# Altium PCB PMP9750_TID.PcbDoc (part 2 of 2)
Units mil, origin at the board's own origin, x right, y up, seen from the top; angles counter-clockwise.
Board outline 3800 x 2050 mil, 2 copper layers (Top Layer, Bottom Layer), stack 62 mil thick; 72 components, 37 nets, 177 pads, 17 vias.
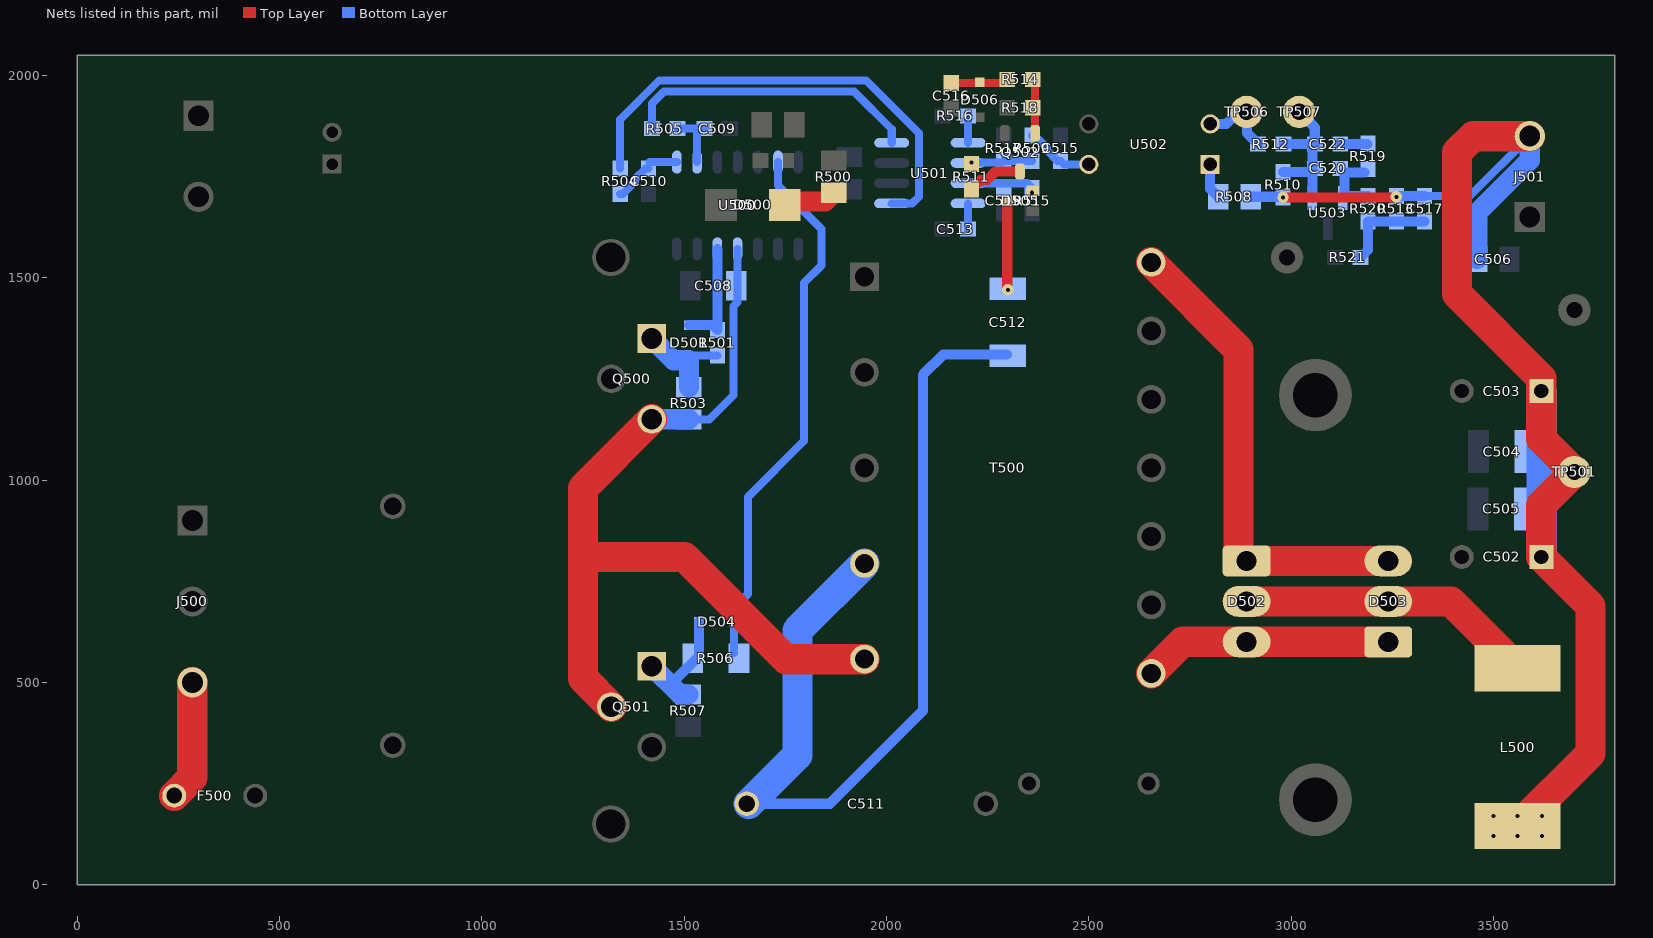
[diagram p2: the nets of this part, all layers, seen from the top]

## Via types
v1: diameter 28, hole 10, Top Layer to Bottom Layer, 17 vias

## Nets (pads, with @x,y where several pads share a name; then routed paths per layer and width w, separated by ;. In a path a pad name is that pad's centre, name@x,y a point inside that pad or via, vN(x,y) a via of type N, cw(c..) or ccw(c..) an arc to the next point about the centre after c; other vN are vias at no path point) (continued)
NetC508_2: C508.2 Q500.3 Q501.2 R503.2 T500.5 U500.11 | length 2162.4
  Top Layer w75: 1290,810 1500,810 1752.44,557.56 T500.5@1945.67,557.56 ; Q501.2@1320,440 1250,510 1250,980 Q500.3@1420,1150
  Bottom Layer w20: R503.2@1512,1149.6 1562,1149.6 1622,1209.6 1622,1429.6 1632,1439.6 U500.11@1632,1571.22
  Bottom Layer w50: Q500.3@1420,1150 1511.6,1150 R503.2@1512,1149.6
NetC509_1: C509.1 R505.2 U500.2 | length 139.7
  Bottom Layer w20: R505.2@1483.5,1868.5 C509.1@1550.5,1868.5 ; U500.2@1532,1785.78 C509.1@1532,1858.52
NetC510_1: C510.1 R504.2 U500.1 | length 167.1
  Bottom Layer w20: R504.2@1342,1707 1348.34,1707 1378.57,1737.24 1378.57,1743.58 1404.99,1770 C510.1@1412,1770 ; C510.1@1414.72,1785.78 U500.1@1482,1785.78
NetC512_2: C512.2 D505.3 | length 218.5
  Top Layer w25: v1@2298.5,1471.5 D505.3@2298.5,1690
  other v1: 2300,1470
NetC513_1: C513.1 U501.4 | length 63.1
  Bottom Layer w20: C513.1@2201.92,1620.43 U501.4@2201.92,1683.5
NetC515_1: C515.1 R509.2 U502.4 | length 161.3
  Bottom Layer w20: R509.2@2360,1851.5 2366.34,1851.5 2396.57,1821.26 2396.57,1814.92 2422.99,1788.5 C515.1@2430,1788.5 ; C515.1@2438.5,1780 U502.4@2500,1780
NetC516_2: C516.2 D506.1 R514.1 | length 142
  Top Layer w20: C516.2@2160,1981.5 2290,1981.5 R514.1@2298.5,1990
NetC517_2: C517.2 R513.1 R520.2 R521.2 | length 236.2
  Bottom Layer w25: R521.2@3171.5,1550 3190,1568.5 R520.2@3190,1638.5 C517.2@3330,1638.5
NetC519_1: C519.1 D505.2 R515.2 U501.3 | length 163.1
  Bottom Layer w20: U501.3@2201.92,1733.5 2348,1733.5 R515.2@2360,1721.5
  other v1: 2360,1710
NetC520_1: C520.1 R519.2 R520.1 U503.2 | length 167
  Bottom Layer w25: R519.2@3181.5,1760 3131.5,1760 3131.5,1701.5 R520.1@3190,1701.5
NetC520_2: C520.2 C522.2 R510.1 R512.2 TP507.1 U503.1 | length 360.3
  Bottom Layer w25: R510.1@2980,1761.5 C520.2@3044.09,1761.5 ; R512.2@2981.5,1830 3046.69,1830 3052.6,1824.09 U503.1@3052.6,1697.4 ; TP507.1@3020,1910 3058.5,1871.5 C522.2@3058.5,1830
NetC522_1: C522.1 R519.1 | length 67
  Bottom Layer w25: C522.1@3121.5,1830 R519.1@3188.5,1830
NetD500_2: D500.2 R500.2 | length 138.2
  Top Layer w50: D500.2@1740.74,1688.5 1848.5,1688.5 R500.2@1870,1710
NetD501_1: D501.1 R501.1 U500.12 | length 275
  Bottom Layer w25: D501.1@1512,1382.91 1570.19,1382.91 R501.1@1582,1371.1 U500.12@1582,1571.22
NetD501_2: D501.2 Q500.1 R501.2 R503.1 | length 255.8
  Bottom Layer w20: D501.2@1512,1296.3 1523.81,1308.11 R501.2@1582,1308.11
  Bottom Layer w50: Q500.1@1420,1350 1473.7,1296.3 D501.2@1512,1296.3 R503.1@1512,1229.6
NetD502_1: D502.1 D503.3 T500.12 | length 1185.5
  Top Layer w75: T500.12@2654.33,1537.87 2870,1322.2 2870,820 D502.1@2890,800 D503.3@3240,800
NetD502_3: D502.3 D503.1 T500.6 | length 617.9
  Top Layer w75: T500.6@2654.33,522.13 2732.2,600 D502.3@2890,600 D503.1@3240,600
NetD504_1: D504.1 R506.1 U500.6 | length 1347.5
  Bottom Layer w20: R506.1@1623.31,572.44 D504.1@1623.31,650 1623.31,683.89 1657.87,718.45 1657.87,958.45 1795.75,1096.33 1795.75,1486.83 1839.56,1530.64 1839.56,1620.36 1732,1727.92 U500.6@1732,1785.78
NetD504_2: D504.2 Q501.1 R506.2 R507.1 | length 278.4
  Bottom Layer w25: 1484.17,512.36 1536.69,564.88 D504.2@1536.69,650
  Bottom Layer w50: Q501.1@1420,540 1490,470 R507.1@1510,470
NetF500_2: F500.2 J500.3 | length 298.6
  Top Layer w75: F500.2@240,220 284.83,264.83 J500.3@284.83,500
NetQ502_1: Q502.1 R514.2 R518.1 | length 126.9
  Top Layer w20: Q502.1@2367.4,1857.24 R514.2@2367.4,1984.09
NetQ502_3: Q502.3 R511.1 | length 138.3
  Top Layer w25: R511.1@2210,1718.5 2232.93,1741.44 2249.07,1741.44 2270.39,1762.76 Q502.3@2330,1762.76
NetR504_1: R504.1 U501.5 | length 1184.4
  Bottom Layer w20: R504.1@1342,1770 1342,1891.42 1438.45,1987.87 1949.05,1987.87 2080,1856.93 2080,1700 2063.5,1683.5 U501.5@2012.94,1683.5
NetR505_1: R505.1 U501.8 | length 738.7
  Bottom Layer w20: R505.1@1420.5,1868.5 1420.5,1930.5 1450,1960 1920,1960 2012.94,1867.06 U501.8@2012.94,1833.5
NetR508_1: R508.1 U502.1 | length 88.3
  Bottom Layer w25: U502.1@2800,1780 2800,1720 R508.1@2820,1700
NetR509_1: R509.1 R511.2 R517.2 U501.2 | length 145.9
  Bottom Layer w20: v1(2210,1784.45) R517.2@2285.94,1784.45 ; R517.2@2290,1788.5 R509.1@2360,1788.5
NetR512_1: R512.1 TP506.1 U502.2 | length 194.2
  Bottom Layer w25: U502.2@2800,1880 2840,1880 2870,1910 TP506.1@2890,1910 2891.3,1908.7 2891.3,1857.2 R512.1@2918.5,1830
NetR516_2: R516.2 U501.1 | length 66.1
  Bottom Layer w20: U501.1@2201.92,1833.5 R516.2@2201.92,1899.57
VCS: C511.1 C512.1 T500.4 | length 2295.4
  Bottom Layer w25: C511.1@1660,200 1860,200 2090,430 2090,1260 2140,1310 C512.1@2297.32,1310
  Bottom Layer w75: C511.1@1660,200 1780,320 1780,628.11 T500.4@1945.67,793.78
VOUT: C502.1 C503.1 C504.1 C505.1 C506.1 C517.1 J501.2 L500.2 R508.2 R510.2 R513.2 TP501.1 | length 3718.2
  Top Layer w25: v1(2980,1698.5) v1@3258.5,1698.5
  Top Layer w75: L500.2@3560,145.12 3740,325.12 3740,688.43 C502.1@3618.43,810 3618.43,938.43 TP501.1@3700,1020 3618.43,1101.57 C503.1@3618.43,1220 3618.43,1251.57 3410,1460 3410,1810 3450,1850 J501.2@3590,1850
  Bottom Layer w20: C517.1@3330,1701.5 3441.5,1701.5 J501.2@3590,1850
  Bottom Layer w25: R508.2@2900,1700 R510.2@2978.5,1700 ; R513.2@3260,1701.5 C517.1@3330,1701.5
  Bottom Layer w50: C506.1@3460,1546 3460,1660 3590,1790 J501.2@3590,1850
  Bottom Layer w75: C503.1@3618.43,1220 C502.1@3620,820 ; 3628.43,1020 TP501.1@3700,1020
  other v1: 3500,120 3560,120 3620,120 3500,170 3560,170 3620,170 3260,1700
VSEC: D502.2 D503.2 L500.1 | length 738.4
  Top Layer w75: D502.2@2890,700 D503.2@3240,700 3394.88,700 L500.1@3560,534.88
pads on no net: J500.2 T500.1 T500.2 T500.3 T500.7 T500.9 T500.11 U500.4 U500.8 U500.9 U500.10 U500.14

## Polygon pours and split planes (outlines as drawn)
GND2 on Top Layer "GND2" (solid, remove dead copper, pour order 21): 2780,2020 2800,2040 2830,2040 3770,2040 3790,2020 3790,2000 3790,1860 3790,30 3770,10 3750,10 2640,10 2620,30 2620,100 2620,380 2530,470 2530,480 2530,540 2530,985.04 2530,1260 2600,1330 2610,1340 2610,1570 2640,1600 2780,1740 2780,1768 2780,1910 2780,1950 2780,2020
GND on Top Layer "GND" (solid, remove dead copper, pour order 18): 30,2040 10,2020 10,2000 10,30 30,10 50,10 2360,10 2380,30 2380,60 2380,190 2380,260 2360,280 2230,410 2230,620 2230,870 2230,1250 2230,1510 2420,1700 2520,1800 2520,1830 2520,2020 2500,2040
NetF500_2 on Top Layer "F500_2" (solid, remove dead copper, pour order 16): 170,180 150,200 150,230 150,520 170,540 270,540 320,540 340,520 340,500 340,290 340,200 320,180
VSEC on Top Layer "VSEC" (solid, remove dead copper, pour order 12): 2850,730 2840,720 2840,680 2850,670 2860,670 2920,670 3010,670 3310,670 3350,630 3350,580 3350,500 3350,460 3370,440 3490,440 3650,440 3670,460 3670,480 3670,600 3540,730 3460,730 3380.58,730 3380,729.42 3379.42,730 3260,730
NetD502_1 on Top Layer "D502_1" (solid, remove dead copper, pour order 10): 2610,1570 2620,1580 2680,1580 2730,1580 2740,1580 2920,1400 2930,1390 2930,1370 2930,1300 2930,1160 2930,1150 3000,1080 3100,980 3130,980 3280,980 3300,960 3300,800 3280,780 3270,770 3230,770 2910,770 2850,770 2830,770 2820,780 2820,850 2820,910 2740,990 2740,1060 2740,1370 2610,1500
NetD502_3 on Top Layer "D502_3" (solid, remove dead copper, pour order 8): 2630,540 2630,610 2640,620 2710,620 2784.25,620 3280,620 3290,610 3290,600 3290,570 3290,540 3290,490 3280,480 3270,480 2650,480 2630,500
B+ on Top Layer "B+" (solid, remove dead copper, pour order 4): 400,200 420,180 440,180 520,180 660,180 880,400 1130,650 1130,1020 1324.92,1215.07 1324.92,1260 1324.92,1265.08 1300,1290 1290,1290 1180,1290 950,1060 950,790 400,240
NetC508_2 on Top Layer "C508_2" (solid, remove dead copper, pour order 2): 1410,1190 1390,1170 1360,1140 1230,1010 1230,710 1230,480 1290,420 1307.99,420 1307.99,597.99 1360,650 1380,650 1590,650 1720,520 1860,520 1960,520 1970,520 1990,540 1990,570 1930,630 1840,630 1830,630 1460,1000 1460,1170 1440,1190
GND2 on Bottom Layer "GND2" (solid, remove dead copper, pour order 21): 2780,2020 2800,2040 2830,2040 3770,2040 3790,2020 3790,2000 3790,1860 3790,30 3770,10 3750,10 2640,10 2620,30 2620,100 2620,380 2530,470 2530,480 2530,540 2530,985.04 2530,1260 2600,1330 2610,1340 2610,1570 2640,1600 2780,1740 2780,1768 2780,1910 2780,1950 2780,2020
GND on Bottom Layer "GND" (solid, remove dead copper, pour order 18): 30,2040 10,2020 10,2000 10,30 30,10 50,10 2360,10 2380,30 2380,60 2380,190 2380,260 2360,280 2230,410 2230,620 2230,870 2230,1250 2230,1510 2420,1700 2520,1800 2520,1830 2520,2020 2500,2040
VOUT on Bottom Layer "Vout" (solid, remove dead copper, pour order 14): 3480,20 3460,40 3460,80 3460,220 3480,240 3530,290 3532.87,292.87 3532.87,613.59 3532.87,1172.87 3590,1230 3590.73,1229.27 3636.77,1229.27 3720.73,1229.27 3740,1210 3740,1180 3740,40 3720,20
VCS on Bottom Layer "VCS" (solid, remove dead copper, pour order 6): 1970,840 1990,820 1990,800 1990,780 1990,720 1870,600 1870,580 1870,470 1870,350 1870,250 1840,220 1800,220 1740,220 1730,210 1730,180 1730,170 1720,160 1690,160 1630,160 1620,170 1620,200 1620,210 1620,240 1740,360 1740,380 1740,820 1760,840

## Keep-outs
Keep-Out Layer:
  text ".Layer_Name" at 577,-858.49 h60

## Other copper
Top Layer:
  text ".Layer_Name" at 577,-858.49 h60
Bottom Layer:
  text ".Layer_Name" at 577,-858.49 h60

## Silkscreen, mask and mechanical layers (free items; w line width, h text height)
Top Overlay:
  lines w10: 2060,1840 2200,1840 2230,1870 ; 2410,1910 2430,1910 2440,1920 2480,1920
  text ".PRJ_Number" at 100,1330 h60
  text ".PCB_Rev" at 700,1330 h60
  text "-" at 30,870 h60
  text "NC" at 20,680 h35
  text "+" at 30,470 h60
  text ".Layer_Name" at 577,-858.49 h60
Bottom Overlay:
  lines w10: 1370,1480 1370,1430 1400,1400 1460,1400 ; 2290,1610 2290,1590 2320,1560 2370,1560 2390,1540 2390,1500 ; 2930,1540 2930,1590 2980,1640 2980,1650 ; 3100,1880 3100,1920 3130,1950 3190,1950 ; 3220,1590 3230,1580 3230,1440 ; 3190,1950 3190,2030 3540,2030 3540,1980 3540,1820 3360,1820 3340,1840 3340,1910 3320,1930 3220,1930 3210,1930 3190,1950
  text "-" at 110,870 h60
  text "NC" at 110,670 h35
  text "+" at 110,470 h60
  text ".Layer_Name" at 577,-858.49 h60
Top Paste:
  text ".Layer_Name" at 577,-858.49 h60
Bottom Paste:
  text ".Layer_Name" at 577,-858.49 h60
Top Solder:
  text ".Layer_Name" at 577,-858.49 h60
  text ".Layer_Name" at 577,-858.49 h60
Bottom Solder:
  text ".Layer_Name" at 577,-858.49 h60
Drill Guide:
  text ".Layer_Name" at 577,-858.49 h60
M1 Board Outline:
  the board outline again, w10
  text ".Layer_Name" at 577,-858.49 h60
M2 Board Dimensions:
  rectangle: 125,-400 500,-275
  rectangle: 0,-275 125,-150
  lines w7: 0,-275 1000,-275 ; 125,-400 125,-150 ; 250,-400 250,-150 ; 500,-400 500,-150 ; 750,-400 750,-150 ; 0,-400 0,-150 1000,-150 1000,-400 0,-400
  text ".Layer_Name" at 577,-858.49 h60
M3 3D STEP Top:
  text ".Layer_Name" at 577,-858.49 h60
M4 3D STEP Bottom:
  text ".Layer_Name" at 577,-858.49 h60
M5 Assembly Top:
  lines w10: -292,-930.17 6308,-930.17 ; -292,-726.83 6310,-726.83 ; -292,-523.5 -292,-1133.5 3713,-1133.5 6310,-1133.5 6310,-523.5 -291.5,-523.5 -291.5,-1133.5 1284,-1133.5 ; 2173,-1133.5 2173,-523.5 ; 3440,-726.83 3440,-523.5 ; 4280,-726.83 4280,-523.5 ; 4902,-1140 4902,-937.17
  text "COMPONENTS MARKED 'DNP' SHOULD NOT BE POPULATED." at 1153.5,-318.5 h60
  text "ASSEMBLY VARIANT:" at 1153,-434 h60
  text ".VariantName" at 2189,-434 h60
  text "PCB VIEWED FROM TOP SIDE" at -228.5,-655.67 h60
  text "BOARD #:" at 2248,-655.67 h60
  text ".PRJ_Number" at 2793.5,-655.67 h60
  text "REV:" at 3638,-655.67 h60
  text ".PCB_Rev" at 3929.5,-655.67 h60
  text "SVN REV:" at 4476,-655.67 h60
  text ".VersionControl_RevNumber" at 4982,-655.67 h60
  text "TID #:" at 2248,-859 h60
  text ".TID" at 2793.5,-859 h60
  text "PLOT NAME =" at -228.5,-1064.34 h60
  text ".plot_File_Name" at 577,-1064.34 h60
  text "GENERATED    :" at 2250,-1064.34 h60
  text ".Print_Date" at 3119.5,-1064.34 h60
  text ".Print_Time" at 3848.5,-1064.34 h60
  text "TEXAS INSTRUMENTS" at 5113,-1064.34 h60
M6 Assembly Bottom:
  lines w10: -292.5,-727.33 6309.5,-727.33 ; -290.5,-930.67 6309.5,-930.67 ; 1115.5,-1140.5 1115.5,-937.67 ; 1737.5,-727.33 1737.5,-524 ; 2577.5,-727.33 2577.5,-524 ; 3844.5,-1134 3844.5,-524 ; 4733.5,-1134 6309,-1134 6309,-524 -292.5,-524 -292.5,-1134 2304.5,-1134 6309.5,-1134 6309.5,-524
  text "COMPONENTS MARKED 'DNP' SHOULD NOT BE POPULATED." at 6102,-318 h60
  text ".VariantName" at 5058,-434 h60
  text "ASSEMBLY VARIANT:" at 6097,-434 h60
  text ".VersionControl_RevNumber" at 1035.5,-656.17 h60
  text "SVN REV:" at 1541.5,-656.17 h60
  text ".PCB_Rev" at 2088,-656.17 h60
  text "REV:" at 2379.5,-656.17 h60
  text ".PRJ_Number" at 3224,-656.17 h60
  text "BOARD #:" at 3769.5,-656.17 h60
  text "PCB VIEWED FROM BOTTOM SIDE" at 6246,-656.17 h60
  text ".TID" at 3224,-859.5 h60
  text "TID #:" at 3769.5,-859.5 h60
  text "TEXAS INSTRUMENTS" at 904.5,-1064.84 h60
  text ".Print_Time" at 2169,-1064.84 h60
  text ".Print_Date" at 2898,-1064.84 h60
  text "GENERATED    :" at 3767.5,-1064.84 h60
  text ".plot_File_Name" at 5440.5,-1064.84 h60
  text "PLOT NAME =" at 6246,-1064.84 h60
M9 Title Sheet:
  drawing of 57 lines, arcs and shapes, not listed
  text "1" at 739.84,8036.5 h70
  text "2" at 3235.5,8036.5 h70
  text "3" at 5724.84,8036.5 h70
  text "4" at 8231.51,8036.5 h70
  text "5" at 10730.5,8036.5 h70
  text "6" at 13235.5,8036.5 h70
  text "A" at -416.5,6893.5 h70
  text "A" at 14383.5,6893.5 h70
  text "B" at -416.5,4513.5 h70
  text "B" at 14383.5,4513.5 h70
  text "C" at -416.5,2138.5 h70
  text "C" at 14383.5,2138.5 h70
  text "PROJECT TITLE:" at 11343.5,277.5 h45
  text ".PRJ_Title" at 11393.5,144.17 h70
  text "DESIGNED FOR:" at 11343.5,-23.5 h45
  text ".PRJ_Customer" at 11393.5,-163.5 h70
  text "D" at -416.5,-231.5 h70
  text "D" at 14383.5,-231.5 h70
  text "FILE NAME:" at 11343.5,-323.5 h45
  text ".PCB_File_Name_No_Path" at 11393.5,-443.5 h70
  text "Texas Instruments (TI) and/or its licensors do not warrant the accuracy or completeness of this specification" at 6374,-605.34 h45
  text "ENGINEER:" at 11343.5,-613.5 h45
  text "LAYOUT BY:" at 12848.5,-613.5 h45
  text "or any information contained therein. TI and/or its licensors do not warrant that this design will meet" at 6329.01,-718 h45
  text ".PRJ_Engineer" at 11393.5,-768.49 h70
  text ".PCB_Layout" at 12899,-768.49 h70
  text "the specifications, will be suitable for your application or fit for any particular purpose, or will operate in" at 6329.01,-830.67 h45
  text ".Layer_Name" at 577,-858.49 h60
  text "ALTIUM DESIGNER VERSION:" at 12848.5,-923.5 h45
  text "an implementation. TI and/or its licensors do not warrant that the design is production worthy. You should" at 6329.01,-943.33 h45
  text "completely validate and test your design implementation to confirm the system functionality for your application." at 6374,-1056 h45
  text ".print_Scale" at 11393.5,-1056.83 h70
  text ".Application_BuildNumber" at 12899,-1056.83 h70
  text "1" at 739.84,-1263.5 h70
  text "2" at 3235.5,-1263.5 h70
  text "3" at 5724.84,-1263.5 h70
  text "4" at 8231.51,-1263.5 h70
  text "5" at 10730.5,-1263.5 h70
  text "6" at 13235.5,-1263.5 h70
M10 Fab Notes:
  drawing of 185 lines, arcs and shapes, not listed
  text "DESIGN INFORMATION" at 12381.02,5910 h60
  text "MIN. TRACK WIDTH:" at 11736.46,5730 h60
  text "10" at 12832.7,5730 h60
  text "MIL" at 12987.46,5730 h60
  text "MIN. CLEARANCE:" at 11736.46,5598 h60
  text "0.2" at 12772.7,5598 h60
  text "mm" at 12987.46,5598 h60
  text "MIN. VIA PAD SIZE:" at 11736.46,5466 h60
  text "10" at 12802.71,5466 h60
  text "MIL" at 12987.46,5466 h60
  text "0.05mm (2MIL)" at 12431.46,5324.29 h60
  text "MINIMUM ANNULAR RING" at 11407.23,5320 h60
  text "EXTERNAL" at 13139.46,5320 h60
  text "PER" at 11607.23,5202 h60
  text "IPC-D-275 CLASS 2 LEVEL C" at 11827.23,5202 h60
  text "MIL, HOLES" at 13315.46,5089.71 h60
  text "+/-" at 12923,5089 h60
  text "+/-" at 13777,5089 h60
  text "REGISTRATION TOLERANCES:" at 11407.23,5084 h60
  text "METAL" at 12607,5084 h60
  text "5" at 13183.2,5084 h60
  text "3" at 14016.2,5084 h60
  text "MIL" at 14132.46,5084 h60
  text "MATERIAL:" at 11332.46,4874.54 h60
  text "FR-4 High Tg" at 12318.9,4734.21 h60
  text "FR-408" at 11753.46,4725.64 h60
  text "X" at 12165.46,4725.64 h60
  text "OTHER" at 13241.46,4725.64 h60
  text "62 MIL (1.6mm) +/-10%" at 12073.56,4562.92 h60
  text "THICKNESS:" at 11407.23,4558.64 h60
  text "X" at 11945.4,4558.64 h60
  text "OTHER" at 13358.46,4558.64 h60
  text "TOLERANCE:" at 11407.23,4400.64 h60
  text "X" at 12246.53,4400.64 h60
  text "ANSI IPC-6012 TYPE 3 CLASS 2" at 12433.48,4400.64 h60
  text "OTHER +/-" at 12433.46,4244.64 h60
  text "BOW & TWIST:" at 11407.23,4087.64 h60
  text "X" at 12246.53,4087.64 h60
  text "ANSI IPC-6012 TYPE 3 CLASS 2" at 12433.48,4087.64 h60
  text "OTHER +/-" at 12433.46,3929.13 h60
  text "DRILLING:" at 11332.46,3790.64 h60
  text "REFERENCE:" at 11407.23,3673.64 h60
  text "X" at 12055.46,3673.64 h60
  text "AS SHOWN" at 12242.46,3673.64 h60
  text "X" at 12956.46,3673.64 h60
  text "NC_DRILL FILES" at 13093.46,3673.64 h60
  text "PTH MIN COPPER THICKNESS:" at 11407.23,3515.64 h60
  text "X" at 12757.46,3515.64 h60
  text "1MIL" at 12894.46,3515.64 h60
  text "OTHER" at 13391.46,3515.64 h60
  text "BOARD FINISH:" at 11332.46,3356.64 h60
  text "SILKSCREEN:" at 11487.68,3238.64 h60
  text "X" at 12436.46,3238.64 h60
  text "TOP" at 12562.46,3238.64 h60
  text "X" at 12946.46,3238.64 h60
  text "BOTTOM" at 13073.46,3238.64 h60
  text "SILKSCREEN COLOR:" at 11487.68,3071.64 h60
  text "X" at 12435.42,3071.64 h60
  text "WHITE" at 12562.46,3071.64 h60
  text "OTHER" at 13073.46,3071.64 h60
  text "SOLDER RESIST COLOR:" at 11487.68,2901.64 h60
  text "X" at 12055.42,2742.44 h60
  text "GREEN" at 12182.46,2742.44 h60
  text "BLUE" at 12773.46,2742.44 h60
  text "OTHER" at 13311.46,2742.44 h60
  text "IMMERSION GOLD (ENIG)" at 12393.46,2553.92 h60
  text "ENEPIG" at 13731,2550.64 h60
  text "SURFACE FINISH:" at 11332.46,2549.64 h60
  text "IMM. TIN/SILVER OR EQUIV" at 11662,2392.64 h60
  text "OTHER" at 13093.46,2392.64 h60
  text "X" at 11500,2390 h60
  text "ARRAY/PANEL:" at 11332.46,2213.64 h60
  text "CUT AND TRIM PER MECH LAYER 1" at 12393.46,2209.35 h60
  text "N.C. ROUTE" at 12393.46,2057.64 h60
  text "X" at 13072.46,2057.64 h60
  text "V. SCORE" at 13259.46,2057.64 h60
  text "CERTIFICATION:" at 11332.46,1920.64 h60
  text "MATERIALS AND WORKMANSHIP FOR ALL PCBS" at 12057.46,1920.64 h60
  text "TO MEET OR EXCEED THE REQUIREMENTS OF:" at 12057.46,1822.64 h60
  text "X" at 11683.96,1686.13 h60
  text "ANSI IPC-A-600F CLASS ->" at 11822.96,1686.13 h60
  text "X" at 13462.02,1686.13 h60
  text "2" at 13580.96,1686.14 h60
  text "1" at 13265.96,1684.64 h60
  text "3" at 13934.96,1684.64 h60
  text "X" at 11686.02,1526.64 h60
  text "UL 94V-0" at 11822.96,1526.64 h60
  text "X" at 12498.02,1526.64 h60
  text "RoHS" at 12634.96,1526.64 h60
  text "OTHER" at 13279.36,1526.64 h60
  text "PER ORDER" at 13676.42,1526.64 h60
  text "ADDITIONAL REQUIREMENTS:" at 11332.46,1385.64 h60
  text "MICROSECTION:" at 11407.23,1270.64 h60
  text "YES" at 12312.96,1270.64 h60
  text "REQUIRED" at 13174.46,1114.49 h60
  text "BARE BOARD ELEC. TEST:" at 11407.23,1111.64 h60
  text "NONE" at 12712.96,1111.64 h60
  text "PER ORDER" at 13766.46,1111.64 h60
  text "X" at 12590,1110 h60
  text "MANUFACTURER'S UL:" at 11407.23,954.64 h60
  text "RAIL" at 12572.96,950.35 h60
  text "METAL" at 13064.77,950.35 h60
  text "X" at 13440,950 h60
  text "SILK" at 13576.46,950.35 h60
  text ".Layer_Name" at 577,-858.49 h60
M11 Gerber Information:
  lines w10: -292,-930.17 6308,-930.17 ; -292,-726.83 6310,-726.83 ; -292,-523.5 -292,-1133.5 3713,-1133.5 6310,-1133.5 6310,-523.5 -291.5,-523.5 -291.5,-1133.5 1284,-1133.5 ; 2173,-1133.5 2173,-523.5 ; 3440,-726.83 3440,-523.5 ; 4280,-726.83 4280,-523.5 ; 4902,-1140 4902,-937.17
  text "ALL ARTWORK VIEWED FROM TOP SIDE" at -228.5,-655.67 h60
  text "BOARD #:" at 2248,-655.67 h60
  text ".PRJ_Number" at 2793.5,-655.67 h60
  text "REV:" at 3638,-655.67 h60
  text ".PCB_Rev" at 3929.5,-655.67 h60
  text "SVN REV:" at 4476,-655.67 h60
  text ".VersionControl_RevNumber" at 4982,-655.67 h60
  text "LAYER NAME =" at -228.5,-858.49 h60
  text "TID #:" at 2248,-859 h60
  text ".TID" at 2793.5,-859 h60
  text "PLOT NAME =" at -228.5,-1064.34 h60
  text ".plot_File_Name" at 577,-1064.34 h60
  text "GENERATED    :" at 2250,-1064.34 h60
  text ".Print_Date" at 3119.5,-1064.34 h60
  text ".Print_Time" at 3848.5,-1064.34 h60
  text "TEXAS INSTRUMENTS" at 5113,-1064.34 h60
M12 Stackup:
  drawing of 191 lines, arcs and shapes, not listed
  text "Layer" at 9790.58,7830 h60
  text "Name" at 10200.49,7830 h60
  text "Material" at 11130.23,7830 h60
  text "Thickness" at 11990,7830 h60
  text "Constant" at 12639.84,7830 h60
  text "Board Layer Stack" at 13209.7,7830 h60
  text "1" at 9790.58,7710 h60
  text "Top Overlay" at 10200.49,7710 h60
  text "2" at 9790.58,7590 h60
  text "Top Solder" at 10200.49,7590 h60
  text "Solder Resist" at 11130.23,7590 h60
  text "0.40mil" at 11990,7590 h60
  text "3.5" at 12639.84,7590 h60
  text "3" at 9790.58,7470 h60
  text "Top Layer" at 10200.49,7470 h60
  text "Copper" at 11130.23,7470 h60
  text "1.40mil" at 11990,7470 h60
  text "4" at 9790.58,7350 h60
  text "Dielectric1" at 10200.49,7350 h60
  text "FR-4" at 11130.23,7350 h60
  text "59.20mil" at 11990,7350 h60
  text "4.8" at 12639.84,7350 h60
  text "5" at 9790.58,7230 h60
  text "Bottom Layer" at 10200.49,7230 h60
  text "Copper" at 11130.23,7230 h60
  text "1.40mil" at 11990,7230 h60
  text "6" at 9790.58,7110 h60
  text "Bottom Solder" at 10200.49,7110 h60
  text "Solder Resist" at 11130.23,7110 h60
  text "0.40mil" at 11990,7110 h60
  text "3.5" at 12639.84,7110 h60
  text "7" at 9790.58,6990 h60
  text "Bottom Overlay" at 10200.49,6990 h60
  text ".Layer_Name" at 577,-858.49 h60
M13 Component Bodies Top:
  text ".Layer_Name" at 577,-858.49 h60
M14 Component Bodies Bottom:
  text ".Layer_Name" at 577,-858.49 h60
M15 Courtyards Top:
  text ".Layer_Name" at 577,-858.49 h60
M16 Courtyards Bottom:
  text ".Layer_Name" at 577,-858.49 h60
Drill Drawing:
  drawing of 158 lines, arcs and shapes, not listed
  text "Symbol" at 4119.68,2415.38 h72
  text "Quantity" at 4445.51,2415.38 h72
  text "Finished Hole Size" at 4802.62,2415.38 h72
  text "Plated" at 5464.62,2415.38 h72
  text "Hole Type" at 5748.98,2415.38 h72
  text "17" at 4445.51,2265.92 h60
  text "10.00mil (0.254mm)" at 4802.62,2265.92 h60
  text "PTH" at 5464.62,2265.92 h60
  text "Round" at 5748.98,2265.92 h60
  text "1" at 4445.51,2116.46 h60
  text "28.00mil (0.711mm)" at 4802.62,2116.46 h60
  text "PTH" at 5464.62,2116.46 h60
  text "Round" at 5748.98,2116.46 h60
  text "1" at 4445.51,1967 h60
  text "28.01mil (0.712mm)" at 4802.62,1967 h60
  text "PTH" at 5464.62,1967 h60
  text "Round" at 5748.98,1967 h60
  text "4" at 4445.51,1817.54 h60
  text "33.46mil (0.850mm)" at 4802.62,1817.54 h60
  text "PTH" at 5464.62,1817.54 h60
  text "Round" at 5748.98,1817.54 h60
  text "6" at 4445.51,1668.09 h60
  text "35.43mil (0.900mm)" at 4802.62,1668.09 h60
  text "PTH" at 5464.62,1668.09 h60
  text "Round" at 5748.98,1668.09 h60
  text "2" at 4445.51,1518.63 h60
  text "39.37mil (1.000mm)" at 4802.62,1518.63 h60
  text "PTH" at 5464.62,1518.63 h60
  text "Round" at 5748.98,1518.63 h60
  text "5" at 4445.51,1369.17 h60
  text "40.00mil (1.016mm)" at 4802.62,1369.17 h60
  text "PTH" at 5464.62,1369.17 h60
  text "Round" at 5748.98,1369.17 h60
  text "2" at 4445.51,1219.71 h60
  text "41.34mil (1.050mm)" at 4802.62,1219.71 h60
  text "PTH" at 5464.62,1219.71 h60
  text "Round" at 5748.98,1219.71 h60
  text "2" at 4445.51,1070.25 h60
  text "43.31mil (1.100mm)" at 4802.62,1070.25 h60
  text "PTH" at 5464.62,1070.25 h60
  text "Round" at 5748.98,1070.25 h60
  text "12" at 4445.51,920.79 h60
  text "47.24mil (1.200mm)" at 4802.62,920.79 h60
  text "PTH" at 5464.62,920.79 h60
  text "Round" at 5748.98,920.79 h60
  text "6" at 4445.51,771.33 h60
  text "50.00mil (1.270mm)" at 4802.62,771.33 h60
  text "PTH" at 5464.62,771.33 h60
  text "Round" at 5748.98,771.33 h60
  text "10" at 4445.51,621.87 h60
  text "51.18mil (1.300mm)" at 4802.62,621.87 h60
  text "PTH" at 5464.62,621.87 h60
  text "Round" at 5748.98,621.87 h60
  text "3" at 4445.51,472.42 h60
  text "52.00mil (1.321mm)" at 4802.62,472.42 h60
  text "PTH" at 5464.62,472.42 h60
  text "Round" at 5748.98,472.42 h60
  text "2" at 4445.51,322.96 h60
  text "72.83mil (1.850mm)" at 4802.62,322.96 h60
  text "PTH" at 5464.62,322.96 h60
  text "Round" at 5748.98,322.96 h60
  text "A" at 4110.35,185.95 h49.82
  text "2" at 4445.51,173.5 h60
  text "110.24mil (2.800mm)" at 4802.62,173.5 h60
  text "PTH" at 5464.62,173.5 h60
  text "Round" at 5748.98,173.5 h60
  text "75 Total" at 4445.51,24.04 h60
  text ".Layer_Name" at 577,-858.49 h60

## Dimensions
0,0 to 3800,0 on M2 Board Dimensions
0,0 to 0,2050 on M2 Board Dimensions
0,-400 to 1000,-400 on M2 Board Dimensions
